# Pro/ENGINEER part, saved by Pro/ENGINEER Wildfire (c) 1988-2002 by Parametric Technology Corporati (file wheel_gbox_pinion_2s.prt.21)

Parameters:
  PTNUM = "A_1C_2MYK25024B"
  PTNAME = "SPUR_GEARS-MODULE_2.5"
  MFG = "Stock_Drive_Products"
  WEIGHT = "*"
  MATERIAL = "STEEL"

Other parameters: TEETH, MODULE, OUTSIDE_DIA, PD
